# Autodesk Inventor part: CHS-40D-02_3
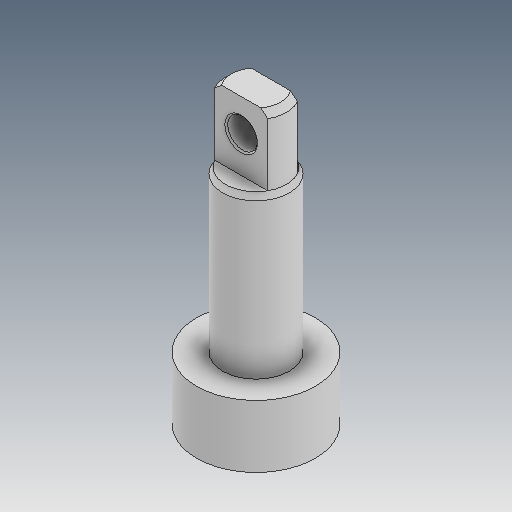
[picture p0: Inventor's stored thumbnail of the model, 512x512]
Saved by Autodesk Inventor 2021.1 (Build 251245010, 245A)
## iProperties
Created: 2019-04
Part Number: CHS-40D-02_3
Material: Ogólny
Document SubType Name: Modeling
Designer: user
Density: 1 g/cm^3
Appearance: Domyślna
Author: user
Revision Number: ÈÎºÎ
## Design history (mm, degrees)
feature "ÊäÈë1"
feature "ÊäÈë2"
node "Bryła1"
node "Bryła2"
